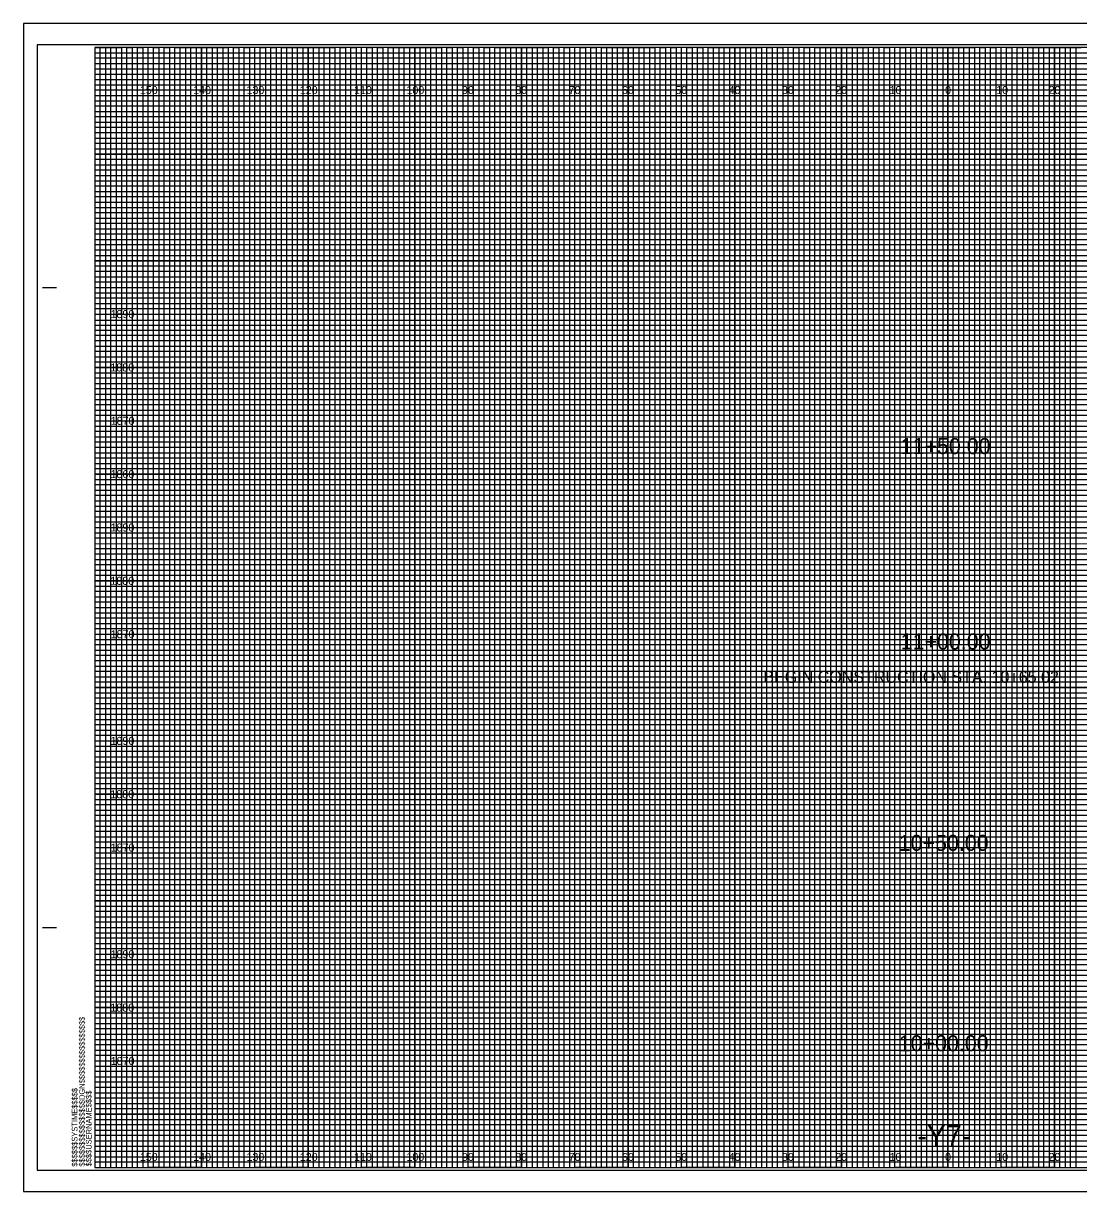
# Model space of a CAD drawing. Extents: x -13 to 323, y -4 to 214.
# Drawn here: x -13.4 to 184.5, y -4.5 to 214.5 of the extents above; entities that cross this region are included whole.
import ezdxf

# ---------------------------------------------------------------- set-up
doc = ezdxf.new("R2010")
doc.units = 0
for name, color, linetype in [('Prop XS Alignment Label', 7, 'Continuous'), ('Prop XS Elevation Labels', 7, 'Continuous'), ('Prop XS Offset Labels', 7, 'Continuous'), ('Prop XS SE Text', 7, 'Continuous'), ('Prop XS Station Labels', 7, 'Continuous'), ('Sheet Cross Section CELL', 7, 'Continuous'), ('Sheet Cross Section Grid Major CELL', 7, 'Continuous'), ('Sheet Cross Section Grid Middle CELL', 7, 'Continuous'), ('Sheet Cross Section Grid Minor 1 CELL', 7, 'Continuous'), ('Sheet Cross Section Grid Minor 2 CELL', 7, 'Continuous'), ('Sheet Cutting Line CELL', 7, 'Continuous'), ('Sheet DOT Grid CELL', 7, 'Continuous'), ('Sheet Plot Border Inside CELL', 7, 'Continuous'), ('Sheet Plot Border Outside CELL', 7, 'Continuous')]:
    doc.layers.add(name, color=color, linetype=linetype)

msp = doc.modelspace()

# ---------------------------------------------------------------- linework, layer by layer
at = {"layer": 'Sheet Cross Section CELL'}
for p, q in [((-9.8, 165), (-7.3, 165)), ((-9.7, 165), (-7.2, 165)), ((-9.8, 45), (-7.3, 45)), ((-9.7, 45), (-7.2, 45))]:
    msp.add_line(p, q, dxfattribs=at)
msp.add_lwpolyline([(320, 210), (0, 210), (0, 0), (320, 0)], close=True, dxfattribs=at)
at = {"layer": 'Sheet Cross Section Grid Major CELL'}
for p, q in [((10, 210), (0, 210)), ((10, 0), (10, 210)), ((30, 210), (20, 210)), ((20, 210), (20, 0)), ((30, 0), (30, 210)), ((50, 210), (40, 210)), ((40, 210), (40, 0)), ((50, 0), (50, 210)), ((70, 210), (60, 210)), ((60, 210), (60, 0)), ((70, 0), (70, 210)), ((90, 210), (80, 210)), ((80, 210), (80, 0)), ((90, 0), (90, 210)), ((110, 210), (100, 210)), ((100, 210), (100, 0)), ((110, 0), (110, 210)), ((130, 210), (120, 210)), ((120, 210), (120, 0)), ((130, 0), (130, 210)), ((150, 210), (140, 210)), ((140, 210), (140, 0)), ((150, 0), (150, 210)), ((170, 210), (160, 210)), ((160, 210), (160, 0)), ((170, 0), (170, 210)), ((190, 210), (180, 210)), ((180, 210), (180, 0)), ((20, 0), (10, 0)), ((40, 0), (30, 0)), ((60, 0), (50, 0)), ((80, 0), (70, 0)), ((100, 0), (90, 0)), ((120, 0), (110, 0)), ((140, 0), (130, 0)), ((160, 0), (150, 0)), ((180, 0), (170, 0))]:
    msp.add_line(p, q, dxfattribs=at)
for points in [[(0, 200), (320, 200), (320, 190), (0, 190)], [(0, 180), (320, 180), (320, 170), (0, 170)], [(0, 160), (320, 160), (320, 150), (0, 150)], [(0, 140), (320, 140), (320, 130), (0, 130)], [(0, 120), (320, 120), (320, 110), (0, 110)], [(0, 100), (320, 100), (320, 90), (0, 90)], [(0, 80), (320, 80), (320, 70), (0, 70)], [(0, 60), (320, 60), (320, 50), (0, 50)], [(0, 40), (320, 40), (320, 30), (0, 30)], [(0, 20), (320, 20), (320, 10), (0, 10)]]:
    msp.add_lwpolyline(points, dxfattribs=at)
at = {"layer": 'Sheet Cross Section Grid Middle CELL'}
for points in [[(0, 210), (5, 210), (5, 0), (15, 0), (15, 210), (25, 210), (25, 0), (35, 0), (35, 210), (45, 210), (45, 0), (55, 0), (55, 210), (65, 210), (65, 0), (75, 0), (75, 210), (85, 210), (85, 0), (95, 0), (95, 210), (105, 210), (105, 0), (115, 0), (115, 210), (125, 210), (125, 0), (135, 0), (135, 210), (145, 210), (145, 0), (155, 0), (155, 210), (165, 210), (165, 0), (175, 0), (175, 210), (185, 210)], [(0, 205), (275, 205)], [(0, 185), (320, 185), (320, 195), (0, 195)], [(0, 165), (320, 165), (320, 175), (0, 175)], [(0, 145), (320, 145), (320, 155), (0, 155)], [(0, 125), (320, 125), (320, 135), (0, 135)], [(0, 105), (320, 105), (320, 115), (0, 115)], [(0, 85), (320, 85), (320, 95), (0, 95)], [(0, 65), (320, 65), (320, 75), (0, 75)], [(0, 45), (320, 45), (320, 55), (0, 55)], [(0, 25), (320, 25), (320, 35), (0, 35)], [(0, 5), (320, 5), (320, 15), (0, 15)]]:
    msp.add_lwpolyline(points, dxfattribs=at)
at = {"layer": 'Sheet Cross Section Grid Minor 1 CELL'}
for p, q in [((0, 209), (260, 209)), ((260, 207.98), (0, 207.98)), ((0, 207.98), (0, 207)), ((0, 207), (260, 207)), ((260, 205.89), (0, 205.89)), ((0, 205.89), (0, 204)), ((0, 204), (320, 204))]:
    msp.add_line(p, q, dxfattribs=at)
for points in [[(0, 203), (270, 203), (320, 203), (320, 202), (0, 202)], [(0, 201), (320, 201), (320, 199), (0, 199)], [(0, 198), (320, 198), (320, 197), (0, 196.98)], [(0, 196), (320, 196), (320, 194), (0, 194)], [(0, 193), (320, 193), (320, 192), (0, 192)], [(0, 191), (320, 191), (320, 189), (0, 189)], [(0, 188), (320, 188), (320, 187), (0, 187)], [(0, 186), (320, 186), (320, 184), (0, 184)], [(0, 183), (320, 183), (320, 182), (0, 182)], [(0, 181), (320, 181), (320, 179), (0, 179)], [(0, 178), (320, 178), (320, 177), (0, 177)], [(0, 176), (320, 176), (320, 173.95), (320, 173), (320, 172), (0, 172)], [(0, 174), (320, 174), (320, 173), (0, 173)], [(0, 171), (320, 171), (320, 169), (0, 169.03)], [(0, 169.03), (320, 169), (320, 168), (0, 168)], [(0, 167), (320, 167), (320, 166), (0, 166)], [(0, 164), (320, 164), (320, 163), (0, 163)], [(0, 162), (320, 162), (320, 161), (0, 161)], [(-0.07, 158.89), (320, 158.89), (320, 157.88), (-0.07, 157.88)], [(0, 157), (320, 157), (320, 156), (0, 156)], [(0, 154), (320, 154), (320, 153), (0, 153)], [(0, 152), (320, 152), (320, 151), (0, 151)], [(0, 149), (320, 149), (320, 148), (0, 148)], [(0, 147), (320, 147), (320, 146), (0, 146)], [(0, 144), (320, 144), (320, 143), (0, 143)], [(0, 142), (320, 142), (320, 141), (0, 141)], [(0, 139), (320, 139), (319.99, 137.98), (0, 138)], [(0, 137), (320, 137), (320, 136), (0, 136)], [(0, 134), (320, 134), (320, 133), (0, 133)], [(0, 132), (320, 132), (320, 131), (0, 131)], [(0, 129), (320, 129), (320, 128), (0, 128)], [(0, 127), (320, 127), (320, 126), (0, 126)], [(0, 124), (320, 124), (320, 123), (0, 123)], [(0, 122), (320, 122), (320, 121), (0, 121)], [(0, 119), (320, 119), (320, 118), (0, 118)], [(0, 116.99), (320.07, 116.91), (320, 116), (0, 116)], [(0, 114), (320, 114), (320, 113), (0, 113)], [(0, 112), (320, 112), (320, 111), (0, 111)], [(0, 109), (320, 109), (320, 108), (0, 108)], [(0, 107), (320, 107), (320, 106), (0, 106)], [(0, 104), (320, 104), (320, 103), (0, 103)], [(0, 102), (320, 102), (320, 101), (0, 101)], [(0, 99), (320, 99), (320, 98), (0, 98)], [(0, 97), (320, 97), (320, 96), (0, 96)], [(0, 94), (320, 94), (320, 93), (0, 93)], [(0, 92), (320, 92), (320, 91), (0, 91)], [(0, 89), (320, 89), (320, 88), (0, 88)], [(0, 87), (320, 87), (320, 86), (0, 86)], [(0, 84), (320, 84), (320, 83), (0, 83)], [(0, 82), (320, 82), (320, 81), (0, 81)], [(0, 79), (320, 79), (319.99, 77.98), (0, 78)], [(0, 77), (320, 77), (320, 76), (0, 76)], [(0, 74), (320, 74), (320, 73), (0, 73)], [(0, 72), (320, 72), (320, 71), (0, 71)], [(0, 69), (320, 69), (320, 68), (0, 68)], [(0, 67), (320, 67), (320, 66), (0, 66)], [(0, 64), (320, 64), (320, 63), (0, 63)], [(0, 62), (320, 62), (320, 61), (0, 61)], [(0, 59), (320, 59), (320, 58), (0, 58)], [(0, 56.99), (320.07, 56.91), (320, 56), (0, 56)], [(0, 54), (320, 54), (320, 53), (0, 53)], [(0, 52), (320, 52), (320, 51), (0, 51)], [(0, 49), (320, 49), (320, 48), (0, 48)], [(0, 47), (320, 47), (320, 46), (0, 46)], [(0, 44), (320, 44), (320, 43), (0, 43)], [(0, 42), (320, 42), (320, 41), (0, 41)], [(0, 39), (320, 39), (320, 38), (0, 38)], [(0, 37), (320, 37), (320, 36), (0, 36)], [(0, 34), (320, 34), (320, 33), (0, 33)], [(0, 32), (320, 32), (320, 31), (0, 31)], [(0, 29), (320, 29), (320, 28), (0, 28)], [(0, 27), (320, 27), (320, 26), (0, 26)], [(0, 24), (320, 24), (320, 23), (0, 23)], [(0, 22), (320, 22), (320, 21), (0, 21)], [(0, 19), (320, 19), (320, 18), (0, 18)], [(0, 17), (320, 17), (320, 16), (0, 16)], [(0, 14), (320, 14), (320, 13), (0, 13)], [(0, 12), (320, 12), (320, 11), (0, 11)], [(0, 9), (320, 9), (320, 8), (0, 8)], [(0, 7), (320, 7), (320, 6), (0, 6)], [(0, 4), (320, 4), (320, 3), (0, 3)], [(0, 2), (320, 2), (320, 1), (0, 1)]]:
    msp.add_lwpolyline(points, dxfattribs=at)
at = {"layer": 'Sheet Cross Section Grid Minor 2 CELL'}
for points in [[(0, 0), (1, 0), (1, 210), (2, 210), (2, 0)], [(2, 0), (3, 0), (3, 210), (4, 210), (4, 0)], [(5, 0), (6, 0), (6, 210), (7, 210), (7, 0)], [(7, 0), (8, 0), (8, 210), (9, 210), (9, 0)], [(10, 0), (11, 0), (11, 210), (12, 210), (12, 0)], [(12, 0), (13, 0), (13, 210), (14, 210), (14, 0)], [(15, 0), (16, 0), (16, 210), (17, 210), (17, 0)], [(17, 0), (18, 0), (18, 210), (19, 210), (19, 0)], [(20, 0), (21, 0), (21, 210), (22, 210), (22, 0)], [(22, 0), (23, 0), (23, 210), (24, 210), (24, 0)], [(25, 0), (26, 0), (26, 210), (27, 210), (27, 0)], [(27, 0), (28, 0), (28, 210), (29, 210), (29, 0)], [(30, 0), (31, 0), (31, 210), (32, 210), (32, 0)], [(32, 0), (33, 0), (33, 210), (34, 210), (34, 0)], [(35, 0), (36, 0), (36, 210), (37, 210), (37, 0)], [(37, 0), (38, 0), (38, 210), (39, 210), (39, 0)], [(40, 0), (41, 0), (41, 210), (42, 210), (42, 0)], [(42, 0), (43, 0), (43, 210), (44, 210), (44, 0)], [(45, 0), (46, 0), (46, 210), (47, 210), (47, 0)], [(47, 0), (48, 0), (48, 210), (49, 210), (49, 0)], [(50, 0), (51, 0), (51, 210), (52, 210), (52, 0)], [(52, 0), (53, 0), (53, 210), (54, 210), (54, 0)], [(55, 0), (56, 0), (56, 210), (57, 210), (57, 0)], [(57, 0), (58, 0), (58, 210), (59, 210), (59, 0)], [(60, 0), (61, 0), (61, 210), (62, 210), (62, 0)], [(62, 0), (63, 0), (63, 210), (64, 210), (64, 0)], [(65, 0), (66, 0), (66, 210), (67, 210), (67, 0)], [(67, 0), (68, 0), (68, 210), (69, 210), (69, 0)], [(70, 0), (71, 0), (71, 210), (72, 210), (72, 0)], [(72, 0), (73, 0), (73, 210), (74, 210), (74, 0)], [(75, 0), (76, 0), (76, 210), (77, 210), (77, 0)], [(77, 0), (78, 0), (78, 210), (79, 210), (79, 0)], [(80, 0), (81, 0), (81, 210), (82, 210), (82, 0)], [(82, 0), (83, 0), (83, 210), (84, 210), (84, 0)], [(85, 0), (86, 0), (86, 210), (87, 210), (87, 0)], [(87, 0), (88, 0), (88, 210), (89, 210), (89, 0)], [(90, 0), (91, 0), (91, 210), (92, 210), (92, 0)], [(92, 0), (93, 0), (93, 210), (94, 210), (94, 0)], [(95, 0), (96, 0), (96, 210), (97, 210), (97, 0)], [(97, 0), (98, 0), (98, 210), (99, 210), (99, 0)], [(100, 0), (101, 0), (101, 210), (102, 210), (102, 0)], [(102, 0), (103, 0), (103, 210), (104, 210), (104, 0)], [(105, 0), (106, 0), (106, 210), (107, 210), (107, 0)], [(107, 0), (108, 0), (108, 210), (109, 210), (109, 0)], [(110, 0), (111, 0), (111, 210), (112, 210), (112, 0)], [(112, 0), (113, 0), (113, 210), (114, 210), (114, 0)], [(115, 0), (116, 0), (116, 210), (117, 210), (117, 0)], [(117, 0), (118, 0), (118, 210), (119, 210), (119, 0)], [(120, 0), (121, 0), (121, 210), (122, 210), (122, 0)], [(122, 0), (123, 0), (123, 210), (124, 210), (124, 0)], [(125, 0), (126, 0), (126, 210), (127, 210), (127, 0)], [(127, 0), (128, 0), (128, 210), (129, 210), (129, 0)], [(130, 0), (131, 0), (131, 210), (132, 210), (132, 0)], [(132, 0), (133, 0), (133, 210), (134, 210), (134, 0)], [(135, 0), (136, 0), (136, 210), (137, 210), (137, 0)], [(137, 0), (138, 0), (138, 210), (139, 210), (139, 0)], [(140, 0), (141, 0), (141, 210), (142, 210), (142, 0)], [(142, 0), (143, 0), (143, 210), (144, 210), (144, 0)], [(145, 0), (146, 0), (146, 210), (147, 210), (147, 0)], [(147, 0), (148, 0), (148, 210), (149, 210), (149, 0)], [(150, 0), (151, 0), (151, 210), (152, 210), (152, 0)], [(152, 0), (153, 0), (153, 210), (154, 210), (154, 0)], [(155, 0), (156, 0), (156, 210), (157, 210), (157, 0)], [(157, 0), (158, 0), (158, 210), (159, 210), (159, 0)], [(160, 0), (161, 0), (161, 210), (162, 210), (162, 0)], [(162, 0), (163, 0), (163, 210), (164, 210), (164, 0)], [(165, 0), (166, 0), (166, 210), (167, 210), (167, 0)], [(167, 0), (168, 0), (168, 210), (169, 210), (169, 0)], [(170, 0), (171, 0), (171, 210), (172, 210), (172, 0)], [(172, 0), (173, 0), (173, 210), (174, 210), (174, 0)], [(175, 0), (176, 0), (176, 210), (177, 210), (177, 0)], [(177, 0), (178, 0), (178, 210), (179, 210), (179, 0)], [(180, 0), (181, 0), (181, 210), (182, 210), (182, 0)], [(182, 0), (183, 0), (183, 210), (184, 210), (184, 0)]]:
    msp.add_lwpolyline(points, dxfattribs=at)
at = {"layer": 'Sheet Cutting Line CELL'}
for p, q in [((323.3, 214.5), (-13.4, 214.5)), ((-13.4, 214.5), (-13.4, -4.5)), ((-13.4, -4.5), (323.3, -4.5))]:
    msp.add_line(p, q, dxfattribs=at)
at = {"layer": 'Sheet DOT Grid CELL'}
for p, q in [((10, 0), (10, 210)), ((20, 0), (20, 210)), ((30, 0), (30, 210)), ((40, 0), (40, 210)), ((50, 0), (50, 210)), ((60, 0), (60, 210)), ((70, 0), (70, 210)), ((80, 0), (80, 210)), ((90, 0), (90, 210)), ((100, 0), (100, 210)), ((110, 0), (110, 210)), ((120, 0), (120, 210)), ((130, 0), (130, 210)), ((140, 0), (140, 210)), ((150, 0), (150, 210)), ((160, 0), (160, 210)), ((170, 0), (170, 210)), ((180, 0), (180, 210)), ((0, 200), (320, 200)), ((0, 190), (320, 190)), ((0, 180), (320, 180)), ((0, 170), (320, 170)), ((0, 160), (320, 160)), ((0, 150), (320, 150)), ((0, 140), (320, 140)), ((0, 130), (320, 130)), ((0, 120), (320, 120)), ((0, 110), (320, 110)), ((0, 100), (320, 100)), ((0, 90), (320, 90)), ((0, 80), (320, 80)), ((0, 70), (320, 70)), ((0, 60), (320, 60)), ((0, 50), (320, 50)), ((0, 40), (320, 40)), ((0, 30), (320, 30)), ((0, 20), (320, 20)), ((0, 10), (320, 10))]:
    msp.add_line(p, q, dxfattribs=at)
at = {"layer": 'Sheet Plot Border Inside CELL'}
msp.add_lwpolyline([(-10.8, -0.5), (322.4, -0.5), (322.4, 210.5), (-10.8, 210.5)], close=True, dxfattribs=at)
at = {"layer": 'Sheet Plot Border Outside CELL'}
msp.add_lwpolyline([(-13.4, -4.5), (323.3, -4.5), (323.3, 214.5), (-13.4, 214.5)], close=True, dxfattribs=at)

# ---------------------------------------------------------------- texts
at = {"layer": 'Prop XS Alignment Label'}
msp.add_text('-Y7-', height=4, dxfattribs=at).set_placement((154.25, 4))
at = {"layer": 'Prop XS Elevation Labels'}
for s, p in [('1890', (2.95, 159.25)), ('1880', (2.92, 149.25)), ('1870', (2.98, 139.25)), ('1860', (2.95, 129.25)), ('1890', (2.95, 119.25)), ('1880', (2.92, 109.25)), ('1870', (2.98, 99.25)), ('1890', (2.95, 79.25)), ('1880', (2.92, 69.25)), ('1870', (2.98, 59.25)), ('1890', (2.95, 39.25)), ('1880', (2.92, 29.25)), ('1870', (2.98, 19.25))]:
    msp.add_text(s, height=1.5, dxfattribs=at).set_placement(p)
at = {"layer": 'Prop XS Offset Labels'}
for s, p in [('150', (8.44, 201.25)), ('140', (18.44, 201.25)), ('130', (28.44, 201.25)), ('120', (38.44, 201.25)), ('110', (48.62, 201.25)), ('100', (58.44, 201.25)), ('90', (68.86, 201.25)), ('80', (78.86, 201.25)), ('70', (88.86, 201.25)), ('60', (98.86, 201.25)), ('50', (108.86, 201.25)), ('40', (118.86, 201.25)), ('30', (128.86, 201.25)), ('20', (138.86, 201.25)), ('10', (149.04, 201.25)), ('0', (159.45, 201.25)), ('0', (159.45, 201.25)), ('10', (169.04, 201.25)), ('20', (178.86, 201.25)), ('150', (8.44, 1.25)), ('140', (18.44, 1.25)), ('130', (28.44, 1.25)), ('120', (38.44, 1.25)), ('110', (48.62, 1.25)), ('100', (58.44, 1.25)), ('90', (68.86, 1.25)), ('80', (78.86, 1.25)), ('70', (88.86, 1.25)), ('60', (98.86, 1.25)), ('50', (108.86, 1.25)), ('40', (118.86, 1.25)), ('30', (128.86, 1.25)), ('20', (138.86, 1.25)), ('10', (149.04, 1.25)), ('0', (159.45, 1.25)), ('0', (159.45, 1.25)), ('10', (169.04, 1.25)), ('20', (178.86, 1.25))]:
    msp.add_text(s, height=1.5, dxfattribs=at).set_placement(p)
at = {"layer": 'Prop XS SE Text'}
msp.add_text('BEGIN CONSTRUCTION STA. 10+65.02', height=2.25, rotation=359.9792, dxfattribs=at).set_placement((125.37, 90.88))
at = {"layer": 'Prop XS Station Labels'}
for s, p in [('11+50.00', (151.13, 133.76)), ('11+00.00', (151.13, 97.13)), ('10+50.00', (150.77, 59.38)), ('10+00.00', (150.77, 21.81))]:
    msp.add_text(s, height=3, dxfattribs=at).set_placement(p)
at = {"layer": 'Sheet Cross Section CELL'}
for s, p in [('$$$$$$$$$$$$$$$$DGN$$$$$$$$$$$$$$$$', (-1.88, 0.18)), ('$$$$$$SYSTIME$$$$$', (-3.26, 0.18)), ('$$$$USERNAME$$$$', (-0.62, 0.23))]:
    msp.add_text(s, height=1.05, rotation=90, dxfattribs=at).set_placement(p)

doc.saveas('drawing.dxf')
